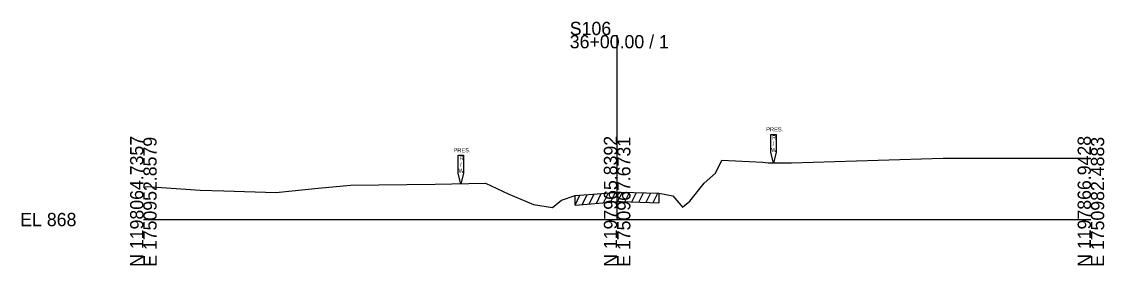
# Model space of a CAD drawing. Extents: x -26 to 1203, y -10 to 19527.
# Drawn here: x 974.3 to 1202.8, y 1990.3 to 2041.9 of the extents above; entities that cross this region are included whole.
import ezdxf

# ---------------------------------------------------------------- set-up
doc = ezdxf.new("R2010")
doc.units = 0
for name, color, linetype in [('RD_GPK_XS_Cell', 7, 'Continuous'), ('RD_XS_ExGround', 7, 'Continuous'), ('RD_XS_ExPaveRet', 7, 'Continuous'), ('RD_XS_ExRW', 7, 'Continuous'), ('RD_XS_TX_Elev_EX', 7, 'Continuous')]:
    doc.layers.add(name, color=color, linetype=linetype)

msp = doc.modelspace()

# ---------------------------------------------------------------- linework, layer by layer
at = {"layer": 'RD_GPK_XS_Cell'}
for p, q in [((1100, 2000), (1100, 2039.01)), ((1000, 2000), (1100, 2000)), ((1100, 2000), (1200, 2000))]:
    msp.add_line(p, q, dxfattribs=at)
at = {"layer": 'RD_XS_ExGround'}
msp.add_lwpolyline([(1000, 2006.88), (1000.82, 2006.99), (1009.92, 2006.36), (1011.99, 2006.22), (1017.01, 2006.07), (1027.99, 2005.75), (1036.87, 2006.62), (1043.71, 2007.28), (1061.6, 2007.47), (1072.24, 2007.67), (1077.01, 2005.44), (1082.35, 2003.2), (1086.33, 2002.53), (1088.24, 2004.12), (1091.11, 2005.06), (1099.5, 2005.74), (1100.2, 2005.8), (1100.87, 2005.8), (1108.77, 2005.57), (1111.74, 2005.03), (1113.46, 2003.05), (1113.8, 2002.65), (1115.33, 2003.9), (1118.37, 2007.7), (1120.76, 2009.78), (1122.12, 2012.57), (1130.73, 2012.12), (1131.85, 2011.99), (1136.8, 2012.01), (1168.83, 2012.98), (1171.22, 2012.98), (1199.11, 2013)], dxfattribs=at)
at = {"layer": 'RD_XS_ExPaveRet'}
for p, q in [((1091.11, 2003.06), (1092.15, 2005.14)), ((1091.11, 2003.06), (1091.11, 2005.06)), ((1092.61, 2003.18), (1093.65, 2005.26)), ((1094.11, 2003.3), (1095.15, 2005.39)), ((1095.61, 2003.42), (1096.65, 2005.51)), ((1097.11, 2003.55), (1098.15, 2005.63)), ((1098.61, 2003.67), (1099.65, 2005.75)), ((1100.11, 2003.79), (1101.11, 2005.79)), ((1101.61, 2003.77), (1102.6, 2005.75)), ((1103.11, 2003.73), (1104.1, 2005.7)), ((1104.61, 2003.69), (1105.6, 2005.66)), ((1106.11, 2003.65), (1107.1, 2005.62)), ((1107.61, 2003.61), (1108.6, 2005.58)), ((1108.77, 2005.57), (1108.77, 2003.57)), ((1091.11, 2003.06), (1099.5, 2003.74)), ((1099.5, 2003.74), (1100.2, 2003.8)), ((1100.2, 2003.8), (1100.87, 2003.8)), ((1100.87, 2003.8), (1108.77, 2003.57))]:
    msp.add_line(p, q, dxfattribs=at)
at = {"layer": 'RD_XS_ExRW'}
for points in [[(1132.45, 2018.01), (1133.55, 2018.01), (1133.55, 2014.18), (1133, 2011.99), (1132.45, 2014.18)], [(1066.45, 2013.59), (1067.55, 2013.59), (1067.55, 2009.76), (1067, 2007.57), (1066.45, 2009.76)]]:
    msp.add_lwpolyline(points, close=True, dxfattribs=at)

# ---------------------------------------------------------------- texts
at = {"layer": 'RD_GPK_XS_Cell'}
for s, p in [('S106', (1090, 2039.01)), ('36+00.00 / 1', (1090, 2036.21)), ('EL 868', (974, 1998.6))]:
    msp.add_text(s, height=2.8, dxfattribs=at).set_placement(p)
for s, p in [('N 1198064.7357', (1000, 1990)), ('E 1750952.8579', (1002.8, 1990)), ('N 1197965.8392', (1100, 1990)), ('E 1750967.6731', (1102.8, 1990)), ('N 1197866.9428', (1200, 1990)), ('E 1750982.4883', (1202.8, 1990))]:
    msp.add_text(s, height=2.8, rotation=90, dxfattribs=at).set_placement(p)
at = {"layer": 'RD_XS_ExRW'}
for s, p in [('PRES.', (1131.45, 2018.63)), ('R', (1132.71, 2016.91)), ('/', (1132.83, 2015.6)), ('PRES.', (1065.45, 2014.22)), ('R', (1066.71, 2012.5)), ('W', (1132.53, 2014.29)), ('/', (1066.83, 2011.19)), ('W', (1066.53, 2009.87))]:
    msp.add_text(s, height=0.875, dxfattribs=at).set_placement(p)
at = {"layer": 'RD_XS_TX_Elev_EX'}
msp.add_text('870.89', height=0.0975, rotation=90, dxfattribs=at).set_placement((1100.1, 2005.78))

doc.saveas('drawing.dxf')
